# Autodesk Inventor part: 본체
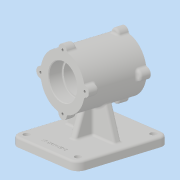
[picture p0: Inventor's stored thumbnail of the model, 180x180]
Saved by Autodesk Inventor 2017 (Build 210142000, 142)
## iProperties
Part Number: 본체
Material: 일반
Document SubType Name: Modeling
Designer: MRC
Density: 1 g/cm^3
Appearance: 기본값
Mass: 452.843 g
Surface Area: 800.379 cm^2
Volume: 452.843 cm^3
Author: MRC
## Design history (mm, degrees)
sketch "스케치2"
  geometry: L1 (0, 0)-(0, 43.5); L2 (37, 0)-(37, 43.5); L3 (37, 43.5)-(23.5, 43.5); L4 (23.5, 43.5)-(23.5, 24.5); L5 (23.5, 24.5)-(21, 24.5); L6 (21, 24.5)-(21, 0); L7 (21, 0)-(37, 0); L8 (37, 0)-(37, -43.5); L9 (37, -43.5)-(23.5, -43.5); L10 (23.5, -43.5)-(23.5, -24.5); L11 (23.5, -24.5)-(21, -24.5); L12 (21, -24.5)-(21, 0); 1 further point
  constraints: 24 end point, 5 perpendicular, 4 symmetric about line, 2 vertical, 1 horizontal alignment, 1 midpoint
  dimensions: "d3" = 43.5 distance of L1.start L1.end; "d4" = 47 diameter of L4 L1; "d5" = 42 diameter of L6 L1; "d6" = 43.5 distance of L2.start L2.end; "d7" = 74 diameter of L2 L1; "d8" = 19 distance between parallel lines of L3 L5
revolve "회전1" sketch "스케치2" stored, may be unused: angle "d9" = 90 deg
sketch "스케치3"
  geometry: C1 r 7 at (0, 37); 1 further point
  constraints: 1 centre point, 1 vertical alignment
  dimensions: "d10" = 14 diameter of C1; "d11" = 37 distance of point (0, 0) C1.centre
extrude "돌출1" join sketch "스케치3" distance "d12" = 14; taper "d13" = 0 deg
sketch "스케치4"
  geometry: 2 further points
  constraints: 1 vertical alignment
  dimensions: "d14" = 37 distance of point (0, -37) point (0, 0)
hole "구멍1" sketch "스케치4" at (0, 0) diameter "d15" = 3.242; stored, may be unused: countersink angle "d19" = 90 deg, drill point angle "d21" = 118 deg; dims "d16" = 8, "d17" = 4, "d18" = 2, "d20" = 10
node "작업 평면1"
sketch "스케치5"
  geometry: L1 (43, -60)-(-43, -60); L2 (-55, -48)-(-55, 58); L3 (-43, 70)-(43, 70); L4 (55, 58)-(55, -48); A1 r 12 centre (43, -48) between (43, -60) and (55, -48); A2 r 12 centre (-43, -48) between (-55, -48) and (-43, -60); A3 r 12 centre (-43, 58) between (-43, 70) and (-55, 58); A4 r 12 centre (43, 58) between (55, 58) and (43, 70); 4 further points
  constraints: 8 end point, 8 point on circle, 8 tangent, 6 point on line, 4 centre point, 3 equal radius, 2 parallel, 1 horizontal, 1 perpendicular
  dimensions: "d26" = 130 distance of point (-55, -60) point (-55, 70); "d27" = 110 distance of point (55, -60) point (-55, -60); "d28" = 70 distance from line of L3 point (0, 0); "d29" = 55 distance from line of L4 point (0, 0); "d30" = 12 radius of A1
extrude "돌출2" join sketch "스케치5" distance "d31" = 12; taper "d32" = 0 deg
sketch "스케치7"
  geometry: L1 (-5, 5)-(5, 5); L2 (5, 5)-(5, -5); L3 (5, -5)-(-5, -5); L4 (-5, -5)-(-5, 5); 3 further points
  constraints: 8 end point, 2 midpoint, 2 parallel, 1 horizontal, 1 horizontal alignment, 1 perpendicular, 1 vertical alignment
  dimensions: "d52" = 10 distance of L1.start L1.end; "d53" = 10 distance of L1.end L2.end
extrude "돌출4" join sketch "스케치7" stored distance "d54" = 80; taper "d55" = 0 deg
sketch "스케치8"
  geometry: L1 (-41, -70)-(-25.336, -26.964); L2 (25.336, -26.964)-(41, -70); L3 (43, -70)-(-43, -70) reference; L4 (-55, -82)-(-55, -70) reference; L5 (55, -82)-(55, -70) reference; A1 r 37 centre (0, 0) between (-36.338, -6.969) and (-6.969, -36.338) reference; A2 r 37 centre (0, 0) between (6.969, -36.338) and (36.338, -6.969) reference; 1 further point
  constraints: 4 end point, 2 point on circle, 2 point on line
  dimensions: "d56" = 14 distance from line of L1.start L4; "d57" = 14 distance from line of L5 L2.end; "d58" = 110 deg dimension on L1.start L4.end L1.end; "d59" = 110 deg dimension on L2.end L5.end L2.start
feature "리브1" dims "d60" = 1, "d61" = 10, "d62" = 0, "d63" = 0, "d64" = 1, "d65" = 1
feature "리브2" dims "d66" = 1, "d67" = 10, "d68" = 0, "d69" = 0, "d70" = 1, "d71" = 1
sketch "스케치9"
  geometry: L1 (-70, 30)-(-37, 17.989); L2 (-37, -17.989)-(-70, -30); L3 (-37, 29.5)-(-37, -29.5) reference; L4 (-70, -48)-(-70, 58) reference; 1 further point
  constraints: 4 end point, 4 point on line
  dimensions: "d72" = 60 distance of L2.end L1.start; "d73" = 30 vertical distance of L1.start point (0, 0); "d74" = 110 deg dimension on L1.start L1.end L4.end; "d75" = 110 deg dimension on L2.end L4.start L2.start
feature "리브3" dims "d76" = 1, "d77" = 10, "d78" = 0, "d79" = 0, "d80" = 1, "d81" = 1
feature "리브4" dims "d82" = 1, "d83" = 10, "d84" = 0, "d85" = 0, "d86" = 1, "d87" = 1
fillet "모깎기1" dims "d88" = 1
chamfer "모따기1" distance "d89" = 1; stored, may be unused: second distance "d90" = 2, angle "d91" = 45 deg
fillet "모깎기2" dims "d92" = 3
fillet "모깎기3" dims "d93" = 3
sketch "스케치10"
  geometry: L1 (43, 60)-(-43, 60) reference; L2 (-55, 48)-(-55, -58) reference; C1 r 4.5 at (-43, 48); 1 further point
  constraints: 1 centre point
  dimensions: "d94" = 9 diameter of C1; "d96" = 12 distance from line of L2 C1.centre; "d97" = 12 distance from line of L1 C1.centre
extrude "돌출5" cut sketch "스케치10" stored distance "d98" = 80; taper "d99" = 0 deg
sketch "스케치11"
  geometry: 2 further points
  constraints: 1 vertical alignment, 1 other
  dimensions: "d106" = 55 distance of point (0, 0) point (0, -55)
feature "엠보싱1" sketch "스케치11" dims "d3" = 43.5, "d4" = 47, "d5" = 42, "d6" = 43.5, "d7" = 74, "d8" = 19, "d107" = 0.5, "d108" = 0
node "솔리드1"
pattern_circular "원형 패턴1" dims angle "d23" = 360 deg
mirror "미러1"
pattern_linear "직사각형 패턴1" dims "d102" = 86, "d105" = 106
other parameters: "d25" = -82
